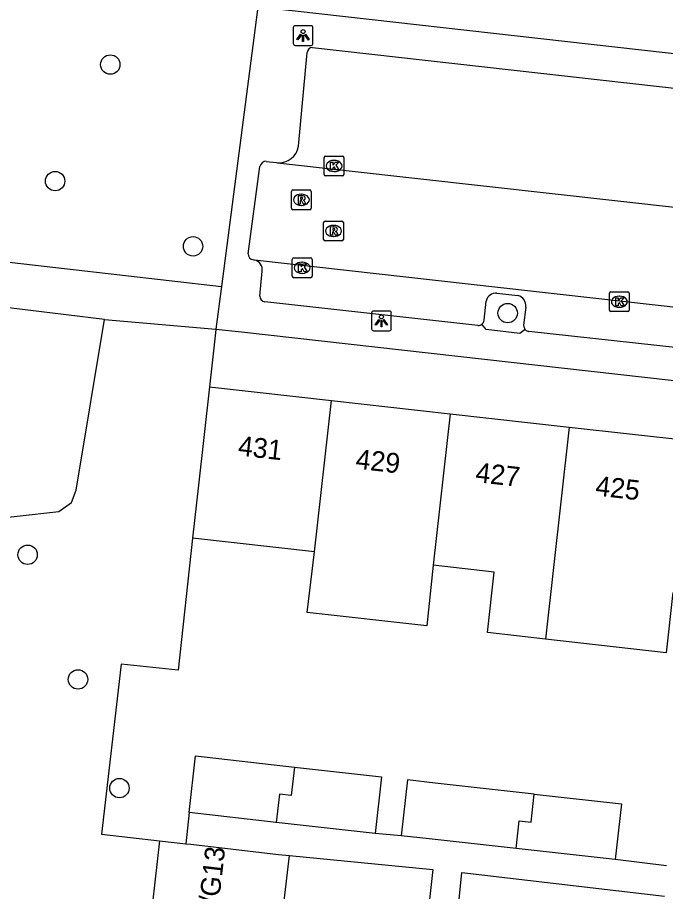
# Model space of a CAD drawing. Extents: x 161928 to 163055, y 386475 to 387428.
# Drawn here: x 162031.23 to 162063.92, y 386907.42 to 386951.52 of the extents above; entities that cross this region are included whole.
import ezdxf

# ---------------------------------------------------------------- set-up
doc = ezdxf.new("R2010")
doc.units = 0
for name, color, linetype in [('IMGEO_Boom', 7, 'Continuous'), ('IMGEO_Groenvoorziening', 7, 'Continuous'), ('IMGEO_Kolk', 7, 'Continuous'), ('IMGEO_Lichtpunt', 7, 'Continuous'), ('IMGEO_Pand', 7, 'Continuous'), ('IMGEO_Pand_nummerreeks', 7, 'Continuous'), ('IMGEO_Parkeervlak_open', 7, 'Continuous'), ('IMGEO_Rijbaan_lokaal_open', 7, 'Continuous'), ('IMGEO_Rioolput', 7, 'Continuous'), ('IMGEO_Voetpad_open', 7, 'Continuous')]:
    doc.layers.add(name, color=color, linetype=linetype)

msp = doc.modelspace()

# ---------------------------------------------------------------- linework, layer by layer
at = {"layer": 'IMGEO_Boom'}
for centre in [(162035.912, 386949.14), (162033.13, 386943.26), (162040.087, 386939.97), (162055.958, 386936.601), (162031.742, 386924.412), (162034.283, 386918.122), (162036.373, 386912.638)]:
    msp.add_circle(centre, 0.489, dxfattribs=at)
at = {"layer": 'IMGEO_Groenvoorziening'}
for points in [[(162029.159, 386843.54), (162024.396, 386843.826), (162025.973, 386854.444), (162024.437, 386856.286), (162022.038, 386857.975), (162029.099, 386926.127), (162033.315, 386926.597), (162033.962, 386927.041), (162034.191, 386927.676), (162035.618, 386936.278)], [(162041.235, 386935.798), (162041.225, 386935.599), (162040.921, 386932.883)], [(162040.065, 386925.24), (162039.338, 386918.584), (162036.452, 386918.899), (162035.472, 386910.317), (162038.399, 386909.983)]]:
    msp.add_lwpolyline(points, dxfattribs=at)
at = {"layer": 'IMGEO_Kolk'}
for p, q in [((162046.698, 386943.599), (162046.698, 386944.451)), ((162046.773, 386944.525), (162047.625, 386944.525)), ((162047.186, 386944.305), (162047.211, 386944.305)), ((162047.699, 386944.451), (162047.699, 386943.599)), ((162047.209, 386943.745), (162047.184, 386943.745)), ((162047.625, 386943.525), (162046.773, 386943.525)), ((162045.092, 386938.462), (162045.092, 386939.314)), ((162045.167, 386939.388), (162046.019, 386939.388)), ((162046.093, 386939.314), (162046.093, 386938.462)), ((162045.58, 386939.168), (162045.605, 386939.168)), ((162045.603, 386938.608), (162045.578, 386938.608)), ((162046.019, 386938.388), (162045.167, 386938.388)), ((162061.09, 386936.75), (162061.09, 386937.602)), ((162061.165, 386937.676), (162062.017, 386937.676)), ((162062.091, 386937.602), (162062.091, 386936.75)), ((162061.578, 386937.456), (162061.603, 386937.456)), ((162062.017, 386936.676), (162061.165, 386936.676)), ((162061.601, 386936.896), (162061.576, 386936.896))]:
    msp.add_line(p, q, dxfattribs=at)
for points in [[(162046.698, 386943.599), (162046.698, 386944.451)], [(162046.773, 386944.525), (162047.625, 386944.525)], [(162047.019, 386944.225), (162047.142, 386944.225), (162047.142, 386944.074), (162047.272, 386944.225), (162047.436, 386944.225), (162047.29, 386944.074), (162047.443, 386943.825), (162047.291, 386943.825), (162047.206, 386943.989), (162047.142, 386943.922), (162047.142, 386943.825), (162047.019, 386943.825), (162047.019, 386944.225)], [(162047.699, 386944.451), (162047.699, 386943.599)], [(162047.625, 386943.525), (162046.773, 386943.525)], [(162045.092, 386938.462), (162045.092, 386939.314)], [(162045.167, 386939.388), (162046.019, 386939.388)], [(162046.093, 386939.314), (162046.093, 386938.462)], [(162045.413, 386939.088), (162045.536, 386939.088), (162045.536, 386938.937), (162045.666, 386939.088), (162045.83, 386939.088), (162045.684, 386938.937), (162045.837, 386938.688), (162045.685, 386938.688), (162045.6, 386938.852), (162045.536, 386938.785), (162045.536, 386938.688), (162045.413, 386938.688), (162045.413, 386939.088)], [(162046.019, 386938.388), (162045.167, 386938.388)], [(162061.09, 386936.75), (162061.09, 386937.602)], [(162061.165, 386937.676), (162062.017, 386937.676)], [(162062.091, 386937.602), (162062.091, 386936.75)], [(162061.411, 386937.376), (162061.534, 386937.376), (162061.534, 386937.225), (162061.664, 386937.376), (162061.828, 386937.376), (162061.682, 386937.225), (162061.835, 386936.976), (162061.683, 386936.976), (162061.598, 386937.14), (162061.534, 386937.073), (162061.534, 386936.976), (162061.411, 386936.976), (162061.411, 386937.376)], [(162062.017, 386936.676), (162061.165, 386936.676)]]:
    msp.add_lwpolyline(points, dxfattribs=at)
for centre, start, end in [((162046.775, 386944.449), 91.552, 178.448), ((162046.775, 386944.449), 91.552, 178.448), ((162047.623, 386944.449), 1.552, 88.448), ((162047.623, 386944.449), 1.552, 88.448), ((162046.775, 386943.601), 181.552, 268.448), ((162046.775, 386943.601), 181.552, 268.448), ((162047.623, 386943.601), 271.552, 358.448), ((162047.623, 386943.601), 271.552, 358.448), ((162045.169, 386939.312), 91.552, 178.448), ((162045.169, 386939.312), 91.552, 178.448), ((162046.017, 386939.312), 1.552, 88.448), ((162046.017, 386939.312), 1.552, 88.448), ((162045.169, 386938.464), 181.552, 268.448), ((162045.169, 386938.464), 181.552, 268.448), ((162046.017, 386938.464), 271.552, 358.448), ((162046.017, 386938.464), 271.552, 358.448), ((162061.167, 386937.6), 91.552, 178.448), ((162061.167, 386937.6), 91.552, 178.448), ((162062.015, 386937.6), 1.552, 88.448), ((162062.015, 386937.6), 1.552, 88.448), ((162061.167, 386936.752), 181.552, 268.448), ((162061.167, 386936.752), 181.552, 268.448), ((162062.015, 386936.752), 271.552, 358.448), ((162062.015, 386936.752), 271.552, 358.448)]:
    msp.add_arc(centre, 0.0765, start, end, dxfattribs=at)
for centre, major_axis, ratio, start_param, end_param in [((162047.185, 386944.025), (-0.387, 0.002), 0.722429, 4.712389, 7.853982), ((162047.21, 386944.025), (-0.39, 0.002), 0.717154, 1.570796, 4.712389), ((162045.579, 386938.888), (-0.387, 0.002), 0.722429, 4.712389, 7.853982), ((162045.604, 386938.888), (-0.39, 0.002), 0.717154, 1.570796, 4.712389), ((162061.577, 386937.176), (-0.387, 0.002), 0.722429, 4.712389, 7.853982), ((162061.602, 386937.176), (-0.39, 0.002), 0.717154, 1.570796, 4.712389)]:
    msp.add_ellipse(centre, major_axis=major_axis, ratio=ratio, start_param=start_param, end_param=end_param, dxfattribs=at)
at = {"layer": 'IMGEO_Lichtpunt'}
for p, q in [((162045.139, 386951.007), (162045.139, 386950.2)), ((162045.139, 386951.007), (162045.139, 386950.2)), ((162046.041, 386951.102), (162045.233, 386951.102)), ((162046.041, 386951.102), (162045.233, 386951.102)), ((162046.135, 386950.2), (162046.135, 386951.007)), ((162046.135, 386950.2), (162046.135, 386951.007)), ((162045.233, 386950.106), (162046.041, 386950.106)), ((162045.233, 386950.106), (162046.041, 386950.106)), ((162049.994, 386936.708), (162049.186, 386936.708)), ((162049.994, 386936.708), (162049.186, 386936.708)), ((162049.092, 386936.613), (162049.092, 386935.806)), ((162049.092, 386936.613), (162049.092, 386935.806)), ((162050.088, 386935.806), (162050.088, 386936.613)), ((162050.088, 386935.806), (162050.088, 386936.613)), ((162049.186, 386935.712), (162049.994, 386935.712)), ((162049.186, 386935.712), (162049.994, 386935.712))]:
    msp.add_line(p, q, dxfattribs=at)
for points in [[(162045.513, 386950.671), (162045.552, 386950.643), (162045.364, 386950.381), (162045.326, 386950.408), (162045.513, 386950.671)], [(162045.615, 386950.623), (162045.662, 386950.623), (162045.662, 386950.301), (162045.615, 386950.301), (162045.615, 386950.623)], [(162045.725, 386950.643), (162045.763, 386950.67), (162045.95, 386950.408), (162045.911, 386950.38), (162045.725, 386950.643)], [(162049.466, 386936.277), (162049.505, 386936.249), (162049.317, 386935.987), (162049.279, 386936.014), (162049.466, 386936.277)], [(162049.568, 386936.229), (162049.615, 386936.229), (162049.615, 386935.907), (162049.568, 386935.907), (162049.568, 386936.229)], [(162049.678, 386936.249), (162049.716, 386936.276), (162049.903, 386936.014), (162049.864, 386935.986), (162049.678, 386936.249)]]:
    msp.add_lwpolyline(points, dxfattribs=at)
for centre in [(162045.638, 386950.805), (162049.591, 386936.411)]:
    msp.add_circle(centre, 0.0994, dxfattribs=at)
for centre, start, end in [((162045.233, 386951.007), 90, 180), ((162045.233, 386951.007), 90, 180), ((162046.041, 386951.007), 0, 90), ((162046.041, 386951.007), 0, 90), ((162045.233, 386950.2), 180, 270), ((162045.233, 386950.2), 180, 270), ((162046.041, 386950.2), 270, 0), ((162046.041, 386950.2), 270, 360), ((162049.186, 386936.613), 90, 180), ((162049.186, 386936.613), 90, 180), ((162049.994, 386936.613), 0, 90), ((162049.994, 386936.613), 0, 90), ((162049.186, 386935.806), 180, 270), ((162049.186, 386935.806), 180, 270), ((162049.994, 386935.806), 270, 0), ((162049.994, 386935.806), 270, 360)]:
    msp.add_arc(centre, 0.0946, start, end, dxfattribs=at)
at = {"layer": 'IMGEO_Pand'}
for points in [[(162040.921, 386932.883), (162040.365, 386927.915), (162040.065, 386925.24)], [(162040.921, 386932.883), (162047.066, 386932.195)], [(162046.21, 386924.552), (162047.066, 386932.195)], [(162047.066, 386932.195), (162053.063, 386931.523)], [(162053.063, 386931.523), (162052.207, 386923.88)], [(162053.063, 386931.523), (162059.061, 386930.851)], [(162059.061, 386930.851), (162057.863, 386920.153)], [(162059.061, 386930.851), (162065.149, 386930.169)], [(162046.21, 386924.552), (162040.065, 386925.24)], [(162052.207, 386923.88), (162051.877, 386920.823), (162045.841, 386921.499), (162046.21, 386924.552)], [(162057.863, 386920.153), (162054.934, 386920.481), (162055.278, 386923.536), (162052.207, 386923.88)], [(162064.29, 386922.5), (162063.951, 386919.471), (162057.863, 386920.153)], [(162039.892, 386911.402), (162040.213, 386914.262), (162045.2, 386913.703)], [(162045.2, 386913.703), (162045.04, 386912.271), (162044.443, 386912.338), (162044.283, 386910.91)], [(162045.2, 386913.703), (162049.591, 386913.211), (162049.27, 386910.351)], [(162057.296, 386912.334), (162052.305, 386912.894), (162050.907, 386913.051), (162050.592, 386910.238)], [(162056.384, 386909.59), (162056.541, 386910.994), (162057.138, 386910.927), (162057.296, 386912.334)], [(162057.296, 386912.334), (162061.692, 386911.841), (162061.377, 386909.03)], [(162044.283, 386910.91), (162039.892, 386911.402)], [(162049.27, 386910.351), (162044.582, 386910.876), (162044.283, 386910.91)], [(162056.384, 386909.59), (162051.99, 386910.082), (162050.592, 386910.238)], [(162038.399, 386909.983), (162038.041, 386906.848)], [(162038.399, 386909.983), (162039.716, 386909.832)], [(162039.716, 386909.832), (162039.981, 386909.802), (162044.405, 386909.297), (162044.948, 386909.235)], [(162061.377, 386909.03), (162056.384, 386909.59)], [(162044.59, 386906.099), (162044.948, 386909.235)]]:
    msp.add_lwpolyline(points, dxfattribs=at)
at = {"layer": 'IMGEO_Parkeervlak_open'}
for points in [[(162055.414, 386937.61), (162056.47, 386937.491)], [(162054.768, 386936.242), (162054.876, 386937.209)], [(162056.868, 386936.904), (162056.761, 386935.994)]]:
    msp.add_lwpolyline(points, dxfattribs=at)
for centre, radius, start, end in [((162055.364, 386937.116), 0.497, 84.1955, 169.2028), ((162056.352, 386936.983), 0.522, 351.3062, 76.9702), ((162054.457, 386936.286), 0.314, 308.5739, 351.875), ((162057.078, 386935.983), 0.317, 178.0788, 222.9779)]:
    msp.add_arc(centre, radius, start, end, dxfattribs=at)
at = {"layer": 'IMGEO_Rijbaan_lokaal_open'}
for points in [[(162043.779, 386944.259), (162044.293, 386944.193), (162044.345, 386944.187)], [(162044.345, 386944.187), (162068.437, 386941.485)], [(162042.865, 386939.594), (162043.462, 386943.996)], [(162043.186, 386939.278), (162043.131, 386939.284)], [(162081.961, 386934.925), (162043.186, 386939.278)], [(162044.948, 386909.235), (162052.188, 386908.526), (162048.97, 386879.58), (162048.13, 386872.928)]]:
    msp.add_lwpolyline(points, dxfattribs=at)
for centre, radius, start, end in [((162043.762, 386943.957), 0.303, 86.8135, 172.5483), ((162043.177, 386939.593), 0.312, 179.7502, 261.5133)]:
    msp.add_arc(centre, radius, start, end, dxfattribs=at)
at = {"layer": 'IMGEO_Rioolput'}
for p, q in [((162045.126, 386942.819), (162045.978, 386942.819)), ((162045.051, 386941.893), (162045.051, 386942.745)), ((162045.539, 386942.599), (162045.564, 386942.599)), ((162046.052, 386942.745), (162046.052, 386941.893)), ((162045.562, 386942.039), (162045.537, 386942.039)), ((162045.978, 386941.819), (162045.126, 386941.819)), ((162046.671, 386940.321), (162046.671, 386941.173)), ((162046.746, 386941.247), (162047.598, 386941.247)), ((162047.672, 386941.173), (162047.672, 386940.321)), ((162047.159, 386941.027), (162047.184, 386941.027)), ((162047.598, 386940.247), (162046.746, 386940.247)), ((162047.182, 386940.467), (162047.157, 386940.467))]:
    msp.add_line(p, q, dxfattribs=at)
for points in [[(162045.126, 386942.819), (162045.978, 386942.819)], [(162045.051, 386941.893), (162045.051, 386942.745)], [(162045.64, 386942.517), (162045.388, 386942.519), (162045.388, 386942.119)], [(162045.566, 386942.438), (162045.512, 386942.438), (162045.512, 386942.357)], [(162046.052, 386942.745), (162046.052, 386941.893)], [(162045.388, 386942.119), (162045.512, 386942.119), (162045.512, 386942.281), (162045.523, 386942.281)], [(162045.512, 386942.357), (162045.564, 386942.357)], [(162045.57, 386942.252), (162045.641, 386942.119), (162045.781, 386942.119), (162045.716, 386942.245)], [(162045.978, 386941.819), (162045.126, 386941.819)], [(162046.671, 386940.321), (162046.671, 386941.173)], [(162046.746, 386941.247), (162047.598, 386941.247)], [(162047.672, 386941.173), (162047.672, 386940.321)], [(162047.26, 386940.945), (162047.008, 386940.947), (162047.008, 386940.547)], [(162047.008, 386940.547), (162047.132, 386940.547), (162047.132, 386940.709), (162047.143, 386940.709)], [(162047.186, 386940.866), (162047.132, 386940.866), (162047.132, 386940.785)], [(162047.132, 386940.785), (162047.184, 386940.785)], [(162047.19, 386940.68), (162047.261, 386940.547), (162047.401, 386940.547), (162047.336, 386940.673)], [(162047.598, 386940.247), (162046.746, 386940.247)]]:
    msp.add_lwpolyline(points, dxfattribs=at)
for centre, radius, start, end in [((162045.128, 386942.743), 0.0765, 91.552, 178.448), ((162045.128, 386942.743), 0.0765, 91.552, 178.448), ((162045.976, 386942.743), 0.0765, 1.552, 88.448), ((162045.976, 386942.743), 0.0765, 1.552, 88.448), ((162045.572, 386942.342), 0.0964, 77.0061, 93.1865), ((162045.586, 386942.399), 0.0378, 276.6634, 79.6772), ((162045.639, 386942.407), 0.109, 350.3612, 89.416), ((162045.637, 386942.407), 0.112, 277.5842, 350.9817), ((162045.522, 386942.228), 0.0533, 26.0293, 88.6989), ((162045.548, 386942.546), 0.19, 274.7715, 282.9687), ((162045.621, 386942.192), 0.108, 29.5134, 73.7905), ((162045.128, 386941.895), 0.0765, 181.552, 268.448), ((162045.128, 386941.895), 0.0765, 181.552, 268.448), ((162045.976, 386941.895), 0.0765, 271.552, 358.448), ((162045.976, 386941.895), 0.0765, 271.552, 358.448), ((162046.748, 386941.171), 0.0765, 91.552, 178.448), ((162046.748, 386941.171), 0.0765, 91.552, 178.448), ((162047.596, 386941.171), 0.0765, 1.552, 88.448), ((162047.596, 386941.171), 0.0765, 1.552, 88.448), ((162047.142, 386940.656), 0.0533, 26.0293, 88.6989), ((162047.168, 386940.974), 0.19, 274.7715, 282.9687), ((162047.192, 386940.77), 0.0964, 77.0061, 93.1865), ((162047.206, 386940.827), 0.0378, 276.6634, 79.6772), ((162047.259, 386940.835), 0.109, 350.3612, 89.416), ((162047.257, 386940.835), 0.112, 277.5842, 350.9817), ((162047.241, 386940.62), 0.108, 29.5134, 73.7905), ((162046.748, 386940.323), 0.0765, 181.552, 268.448), ((162046.748, 386940.323), 0.0765, 181.552, 268.448), ((162047.596, 386940.323), 0.0765, 271.552, 358.448), ((162047.596, 386940.323), 0.0765, 271.552, 358.448)]:
    msp.add_arc(centre, radius, start, end, dxfattribs=at)
for centre, major_axis, ratio, start_param, end_param in [((162045.538, 386942.319), (-0.387, 0.002), 0.722429, 4.712389, 7.853982), ((162045.563, 386942.319), (-0.39, 0.002), 0.717154, 1.570796, 4.712389), ((162047.158, 386940.747), (-0.387, 0.002), 0.722429, 4.712389, 7.853982), ((162047.183, 386940.747), (-0.39, 0.002), 0.717154, 1.570796, 4.712389)]:
    msp.add_ellipse(centre, major_axis=major_axis, ratio=ratio, start_param=start_param, end_param=end_param, dxfattribs=at)
at = {"layer": 'IMGEO_Voetpad_open'}
for points in [[(162043.328, 386951.783), (162041.516, 386937.945)], [(162082.412, 386947.656), (162045.239, 386951.832), (162043.361, 386952.034), (162043.328, 386951.783)], [(162046.109, 386950.01), (162067.796, 386947.564)], [(162045.403, 386945.033), (162045.837, 386949.755)], [(162016.546, 386941.814), (162020.393, 386940.366), (162041.516, 386937.945)], [(162043.447, 386937.463), (162043.566, 386938.716)], [(162035.618, 386936.278), (162020.125, 386938.156), (162016.088, 386937.775)], [(162041.516, 386937.945), (162041.235, 386935.798)], [(162054.459, 386935.972), (162043.704, 386937.174)], [(162035.618, 386936.278), (162041.235, 386935.798)], [(162041.235, 386935.798), (162042.531, 386935.656), (162080.492, 386931.393)], [(162056.846, 386935.767), (162056.568, 386935.576), (162054.876, 386935.78), (162054.653, 386936.041)], [(162067.791, 386934.491), (162057.021, 386935.673)], [(162039.892, 386911.402), (162039.716, 386909.832)], [(162050.592, 386910.238), (162049.27, 386910.351)], [(162063.972, 386908.712), (162061.377, 386909.03)], [(162053.496, 386906.858), (162053.642, 386908.384), (162063.867, 386907.179)]]:
    msp.add_lwpolyline(points, dxfattribs=at)
for centre, radius, start, end in [((162046.143, 386949.702), 0.31, 96.2275, 170.0773), ((162044.429, 386945.166), 0.983, 265.0835, 352.2096), ((162043.106, 386938.815), 0.47, 347.8946, 80.2351), ((162043.755, 386937.478), 0.308, 182.7765, 260.5152), ((162054.458, 386936.283), 0.311, 270.2237, 308.9342), ((162057.077, 386935.987), 0.319, 223.5879, 259.9278)]:
    msp.add_arc(centre, radius, start, end, dxfattribs=at)

# ---------------------------------------------------------------- texts
at = {"layer": 'IMGEO_Pand_nummerreeks'}
for s, rotation, p in [('431', 353.6095, (162042.321, 386929.425)), ('429', 353.6095, (162048.255, 386928.76)), ('427', 353.6095, (162054.302, 386928.083)), ('425', 353.6095, (162060.348, 386927.406)), ('407/G13', 83.3997, (162041.124, 386904.53))]:
    msp.add_text(s, height=1, rotation=rotation, dxfattribs=at).set_placement(p)

doc.saveas('drawing.dxf')
